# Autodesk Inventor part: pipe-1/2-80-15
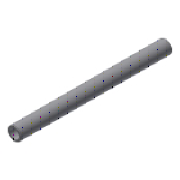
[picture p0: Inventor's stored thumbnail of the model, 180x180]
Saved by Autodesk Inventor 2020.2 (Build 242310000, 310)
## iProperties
Manager: www.cadconsulting.pl
Company: Fabian Stasiak CAD Consulting
Created: 2014-08
Part Number: pipe-1/2-80-15
Material: Ogólny
Document SubType Name: Modeling
Designer: F.Stasiak
Manufacturer: Standard
Standards Organization: Custom
Language: pl-PL
Size Designation: 1/2-80-15
Categories: <MemberInstance><Categories><Category DisplayName="Rury cienko- i grubościenne" InternalName="4347fa0f-2144-441d-94cd-e3e15c92b736" Mnemonic="TUBEANDPIPE"><Cate
Density: 1 g/cm^3
Appearance: Domyślna
Catalog Web Link: www.expertbooks.pl
IsCustomPart: 0
Author: F.Stasiak
Subject: Zbiór ćwiczeń. Autodesk Inventor 2020. Kurs Professional
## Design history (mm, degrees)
node "Punkt konstrukcyjny1"
node "Punkt konstrukcyjny2"
node "Oś konstrukcyjna1"
node "Oś konstrukcyjna2"
body "Solid1"
sketch "Sketch1"
  geometry: C1 r 10.668 at (0, 0); C2 r 6.934 at (0, 0)
  constraints: 2 centre point, 1 coincident
  dimensions: "d0" = 13.8684 diameter of C2 (= ID); "d1" = 21.336 diameter of C1 (= OD)
extrude "Wyciągnięcie proste1" new body sketch "Sketch1" distance "d2" = 381 (= PL); taper "d3" = 0 deg
chamfer "Faza1" distance "d4" = 1.2446 (= t); stored, may be unused: second distance "d5" = 3.175, angle "d6" = 45 deg
other parameters: "OD" = 21.336 [user parameter; used in 2 equation terms], "ID" = 13.8684 [user parameter; used in 2 equation terms], "PL" = 381 [user parameter; used in 1 equation term], "t" = 1.2446 (= -0.166667 x ID + 0.166667 x OD) [user parameter; used in 1 equation term]
